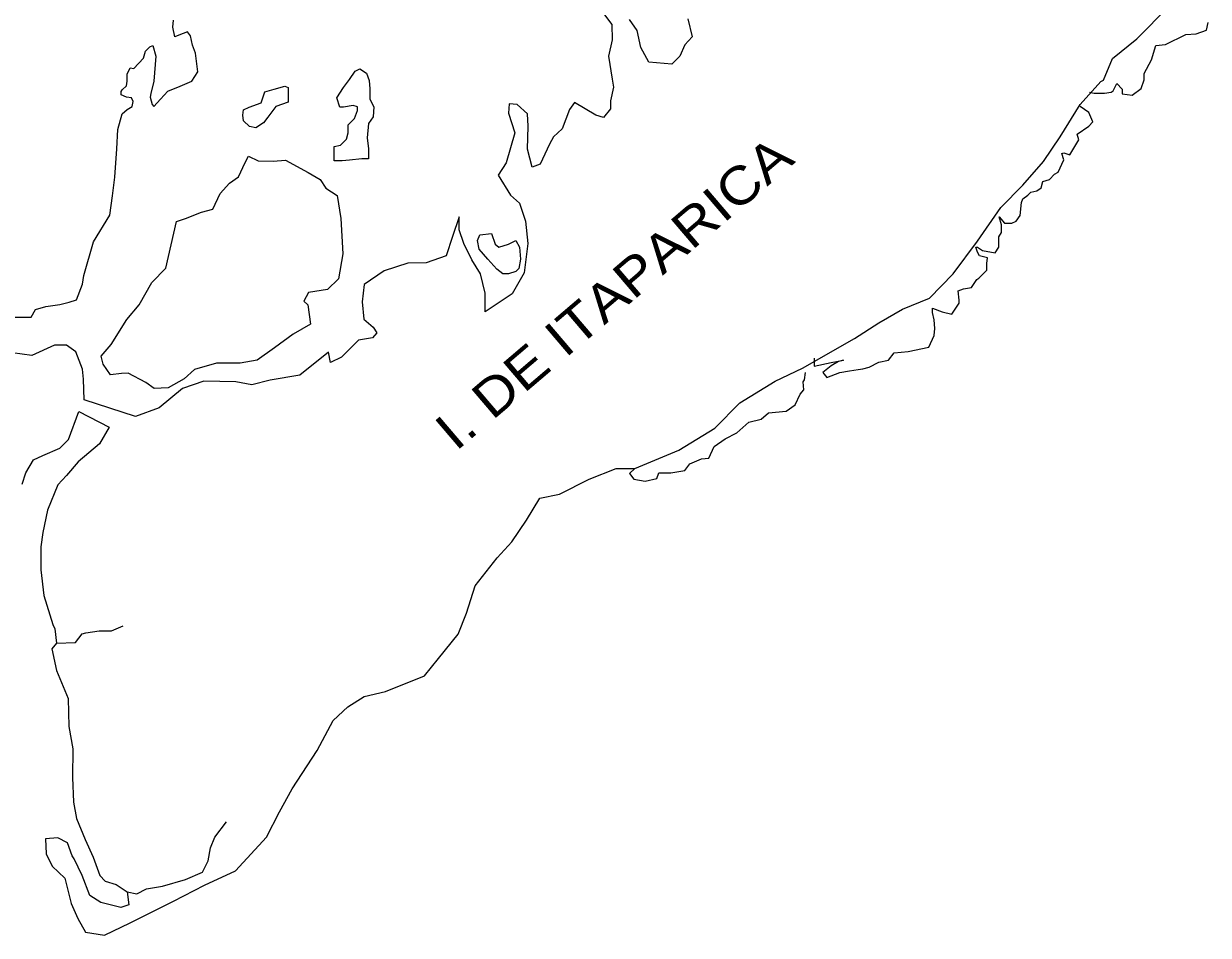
# Model space of a CAD drawing. Extents: x 47169 to 972804, y 7447977 to 9608469.
# Drawn here: x 521076 to 542158, y 8548311 to 8564537 of the extents above; entities that cross this region are included whole.
import ezdxf

# ---------------------------------------------------------------- set-up
doc = ezdxf.new("R2010")
doc.units = 0
doc.header["$LTSCALE"] = 270
doc.layers.add('1', color=7, linetype='Continuous', lineweight=13)
doc.layers.add('3', color=7, linetype='Continuous')

msp = doc.modelspace()

# ---------------------------------------------------------------- linework, layer by layer
at = {"layer": '1'}
for points in [[(524845.6, 8549458.9), (525398.9, 8550055.6), (525627, 8550508.8), (525855, 8550917.8), (526300.1, 8551603), (526582.5, 8552133.6), (526842.9, 8552376.7), (527135.8, 8552564.4), (527515.3, 8552652.4), (528209.3, 8552928.2), (528459, 8553237.6), (528806.4, 8553668.6), (528958.5, 8554044.4), (529110.8, 8554530.8), (529501.7, 8555028.1), (529762.2, 8555315.3), (530022.8, 8555702.1), (530261.8, 8556088.9), (530608.8, 8556165.9), (531140.3, 8556430.8), (531617.6, 8556618.2), (531953.7, 8556617.8), (532734.8, 8556948.7), (533374.9, 8557335), (533820.1, 8557787.8), (534449.4, 8558174.1), (534937.6, 8558405.7), (535860, 8558935.4), (536294.1, 8559211.3), (536717.3, 8559454), (537194.7, 8559652.5), (537618.2, 8560083.2), (538052.7, 8560668.7), (538465.6, 8561265.3), (538856.6, 8561662.9), (539225.9, 8562082.6), (539519.3, 8562524.6), (539878, 8563099.1), (540247.3, 8563507.8), (540290.8, 8563529.8), (540454, 8563916.7), (540888.3, 8564269.9), (541453.1, 8564844.1)], [(531355.8, 8564768.9), (531539.9, 8564525.4), (531550.4, 8564249), (531485.1, 8563961.5), (531549.7, 8563552.2), (531571.2, 8563408.5), (531516.7, 8563165.2), (531516.5, 8563021.5), (531397.1, 8562866.8), (531256.1, 8562911.2), (530876.8, 8563132.8), (530789.9, 8563011.2), (530659.4, 8562668.5), (530507.4, 8562524.9), (530431.3, 8562392.3), (530268.3, 8562038.6), (530127.2, 8561983.5), (530040.8, 8562304.3), (530052.1, 8562713.4), (530041.5, 8562934.6), (529857.3, 8563100.7), (529716.4, 8563111.9), (529705.3, 8562946.1), (529813.4, 8562592.1), (529661, 8562061.4), (529519.8, 8561840.4), (529736.3, 8561486.2), (529898.8, 8561342.3), (530006.9, 8561021.5), (530049.9, 8560623.3)], [(523991.4, 8564389.3), (523839.5, 8564334.1), (523763.6, 8564301), (523731.2, 8564477.9), (523742.2, 8564599.6)], [(532895.7, 8564623.4), (532971.2, 8564302.6), (532840.9, 8564159), (532753.9, 8563960), (532612.8, 8563816.4), (532200.7, 8563850.1), (532060, 8564115.7), (531995.3, 8564414.3), (531854.5, 8564613.6)], [(540041, 8563320.1), (540127.7, 8563297.8), (540312.1, 8563297.6), (540431.4, 8563319.5), (540464, 8563341.6), (540529.3, 8563474.2), (540626.7, 8563374.5), (540626.7, 8563341.3), (540626.6, 8563286), (540800.1, 8563263.7), (540962.9, 8563385.1), (541017.4, 8563539.8), (541017.6, 8563650.4), (541148.1, 8563893.5), (541224.3, 8564147.8), (541397.9, 8564169.6), (541756.1, 8564346), (541940.5, 8564356.8), (542124.9, 8564422.9), (542157.7, 8564555.5)], [(520907.5, 8559315.8), (521081, 8559315.6), (521135.2, 8559315.6), (521211.1, 8559315.5), (521287.2, 8559448.2), (521471.5, 8559503.3), (521721, 8559536.3), (521883.6, 8559580.4), (522013.8, 8559624.5), (522122.5, 8559900.9), (522144.3, 8560055.7), (522318.2, 8560652.8), (522611.4, 8561128.1), (522655.1, 8561470.8), (522698.7, 8561802.6), (522731.7, 8562311.3), (522753.6, 8562654.1), (522829.8, 8562930.5), (522916.6, 8563007.8), (523003.4, 8563063), (523025.2, 8563151.5), (522992.7, 8563217.9), (522905.9, 8563229), (522808.4, 8563273.3), (522808.4, 8563328.6), (522830.1, 8563361.8), (522906.1, 8563428.1), (522917, 8563516.5), (522917.1, 8563638.2), (522971.5, 8563748.7), (523036.5, 8563737.6), (523210.2, 8563925.4), (523242.8, 8564047.1), (523318.8, 8564124.4), (523373, 8564146.5), (523427.1, 8563958.4), (523394.2, 8563516.1), (523339.8, 8563295), (523328.9, 8563228.7), (523361.3, 8563095.9), (523393.8, 8563062.7), (523513.2, 8563195.3), (523643.5, 8563339), (523860.5, 8563427.3), (524066.6, 8563515.5), (524175.2, 8563681.3), (524132.1, 8564013.1), (524078, 8564156.9), (524045.6, 8564322.9), (523991.4, 8564389.3)], [(535143.9, 8558582.4), (535143.7, 8558438.7), (535447.4, 8558504.6), (535664.3, 8558548.6), (535577.5, 8558526.6), (535447.3, 8558449.3), (535295.4, 8558327.9), (535371.2, 8558239.3), (535599, 8558327.5), (535772.5, 8558360.4), (535924.3, 8558382.4), (536011.1, 8558393.3), (536119.6, 8558426.3), (536293.2, 8558514.6), (536466.7, 8558547.5), (536564.4, 8558680.1), (536813.9, 8558701.9), (537182.7, 8558778.8), (537280.5, 8558988.8), (537291.5, 8559110.4), (537280.9, 8559265.3), (537248.5, 8559398), (537248.7, 8559475.4), (537422.1, 8559408.9), (537595.5, 8559364.4), (537725.9, 8559563.3), (537726, 8559618.6), (537704.5, 8559784.5), (537802.1, 8559817.5), (537943.1, 8559839.4), (538040.9, 8559983.1), (538073.5, 8560005.2), (538214.7, 8560148.7), (538214.8, 8560270.4), (538225.8, 8560369.9), (538084.9, 8560403.3), (538052.4, 8560469.7), (538020, 8560558.2), (538052.6, 8560558.1), (538139.2, 8560502.7), (538366.9, 8560458.2), (538432.1, 8560557.6), (538432.2, 8560623.9), (538432.4, 8560745.6), (538475.8, 8560823), (538476, 8560955.7), (538432.8, 8561099.5), (538530.3, 8560988.8), (538660.4, 8560988.6), (538736.4, 8561021.7), (538812.4, 8561121.1), (538834.4, 8561353.3), (538856.2, 8561419.6), (538943.1, 8561485.8), (538997.4, 8561541.1), (539105.8, 8561563), (539181.8, 8561618.2), (539214.5, 8561728.8), (539333.9, 8561761.8), (539420.8, 8561861.2), (539485.9, 8561894.3), (539583.8, 8562115.3), (539551.4, 8562225.9), (539584, 8562236.9), (539692.4, 8562203.6), (539855.4, 8562468.8), (539823, 8562568.4), (540029.3, 8562711.8), (540105.3, 8562789.2), (540029.6, 8562955.1), (539878, 8563065.9)], [(530049.9, 8560623.3), (529984.2, 8560103.6), (529766.9, 8559727.8), (529289.5, 8559407.6), (529289.8, 8559739.4), (529203.5, 8560082.3), (529051.9, 8560336.8), (528911.3, 8560624.5), (528824.8, 8560867.9), (528825, 8561100.2), (528705.4, 8560746.4), (528596.6, 8560403.7), (528238.6, 8560282.4), (527913.3, 8560271.7), (527490.2, 8560139.4), (527132.2, 8559896.4), (527099.3, 8559586.8), (527131.5, 8559277.1), (527294.1, 8559133.2), (527359, 8559033.6), (527283, 8558945.2), (527033.6, 8558901.2), (526729.7, 8558602.9), (526534.4, 8558503.6), (526502.1, 8558691.6), (525992.1, 8558282.9), (525460.7, 8558195), (525135.3, 8558106.8), (524853.4, 8558162.3), (524278.8, 8558173.9), (523899.2, 8558041.5), (523486.9, 8557699.1), (523063.9, 8557544.6), (522153.3, 8557843.9), (522142.8, 8558208.9), (522121.2, 8558385.8), (522002.2, 8558695.6), (521839.7, 8558817.4), (521622.8, 8558817.6), (521221.5, 8558629.9), (520354.1, 8558752.2)], [(531953.7, 8556617.8), (531856.1, 8556529.5), (531931.8, 8556429.8), (532137.8, 8556396.4), (532343.8, 8556440.4), (532376.5, 8556539.9), (532593.3, 8556539.7), (532842.8, 8556583.6), (532929.6, 8556705.1), (533135.8, 8556793.4), (533265.9, 8556804.3), (533363.7, 8557014.3), (533559, 8557146.7), (533765.2, 8557257.1), (533982.3, 8557444.8), (534199.2, 8557499.8), (534329.4, 8557610.3), (534643.9, 8557643.1), (534806.7, 8557753.4), (534893.7, 8557941.3), (534958.8, 8558018.7), (534948.2, 8558162.4), (534969.9, 8558195.6), (534991.8, 8558328.3)], [(521046.2, 8556340.8), (521111.4, 8556539.8), (521252.5, 8556771.9), (521415.2, 8556849.2), (521718.9, 8556981.7), (521870.9, 8557136.4), (522055.6, 8557633.9), (522597.5, 8557357), (522423.8, 8557058.5), (522044, 8556738.1), (521837.8, 8556495), (521685.9, 8556329.2), (521501.2, 8555876), (521414.2, 8555477.9), (521381.5, 8555223.6), (521381.1, 8554814.4), (521435, 8554360.9), (521597.2, 8553841.1), (521629.7, 8553763.6), (521662, 8553509.2), (521575.2, 8553409.8), (521661.6, 8553022.7), (521867.2, 8552524.8), (521877.6, 8552027.2), (521953.2, 8551629), (521941.9, 8551120.3), (521963.3, 8550677.9), (522017.2, 8550390.3), (522168.7, 8550014.2), (522309.3, 8549704.4), (522428.3, 8549372.6), (522525.8, 8549273), (522720.8, 8549217.5), (522915.8, 8549084.6), (522948.2, 8548852.4), (522807.2, 8548808.3), (522449.6, 8548897), (522254.6, 8549018.8), (522114, 8549372.8), (521973.3, 8549671.5), (521940.8, 8549726.9), (521854.3, 8549959.2), (521680.9, 8550047.8), (521464.1, 8550025.8), (521474.8, 8549760.4), (521583, 8549539.1), (521810.4, 8549328.8), (521918.5, 8548875.3), (522037.5, 8548609.8), (522178.2, 8548366.4), (522514.2, 8548310.8), (522969.6, 8548531.6), (523739.5, 8548918.1), (524292.5, 8549205.1), (524845.6, 8549458.9)], [(521662, 8553509.2), (521998.1, 8553520), (522117.4, 8553674.8), (522182.5, 8553696.8), (522421, 8553729.8), (522637.9, 8553729.6), (522843.9, 8553817.9)], [(522915.8, 8549084.6), (523089.2, 8549051.3), (523262.7, 8549139.6), (523544.6, 8549183.6), (523956.6, 8549304.9), (524260.2, 8549437.4), (524357.9, 8549636.3), (524401.5, 8549868.5), (524477.6, 8550056.5), (524683.8, 8550332.8)]]:
    msp.add_lwpolyline(points, dxfattribs=at)
for points in [[(526875.5, 8563546.1), (526973.2, 8563689.8), (527060, 8563734), (527179.2, 8563656.4), (527222.5, 8563523.7), (527233.2, 8563379.9), (527233, 8563191.9), (527308.8, 8563059.1), (527297.8, 8562882.2), (527210.9, 8562760.6), (527188.9, 8562506.3), (527210.4, 8562307.2), (527210.3, 8562130.3), (527091, 8562130.4), (526874.1, 8562108.5), (526743.9, 8562097.5), (526602.9, 8562097.7), (526603.1, 8562241.4), (526603.2, 8562352), (526711.7, 8562374.1), (526820.2, 8562484.5), (526852.8, 8562595.1), (526853, 8562738.9), (526961.6, 8562849.3), (527015.9, 8562993.1), (527016, 8563059.4), (526940.1, 8563081.6), (526766.5, 8563048.6), (526701.5, 8563048.7), (526647.4, 8563214.6), (526766.9, 8563402.5)], [(525302.6, 8563127.4), (525367.8, 8563326.4), (525530.5, 8563370.5), (525725.8, 8563425.6), (525780, 8563403.4), (525779.7, 8563138), (525562.8, 8563060.8), (525421.6, 8562872.9), (525345.6, 8562773.4), (525204.6, 8562685.1), (525096.1, 8562707.3), (524987.8, 8562807), (524977, 8562906.5), (524987.9, 8563006), (525085.6, 8563050.2)], [(523608.3, 8560187.2), (523793.3, 8561016.5), (523956, 8561071.6), (524238.1, 8561182), (524444.1, 8561237.1), (524574.5, 8561513.4), (524737.3, 8561701.3), (524900.1, 8561811.7), (525019.6, 8562066), (525073.9, 8562176.5), (525247.4, 8562098.9), (525518.5, 8562087.7), (525735.4, 8562109.6), (526136.4, 8561888), (526353.2, 8561766.2), (526450.7, 8561611.2), (526656.6, 8561478.3), (526721.2, 8561069.1), (526753.2, 8560438.7), (526676.8, 8559996.4), (526481.5, 8559808.6), (526145.2, 8559753.6), (526058.4, 8559598.9), (526134.2, 8559532.5), (526177.2, 8559189.6), (525873.5, 8559012.9), (525537.1, 8558770), (525233.3, 8558549.1), (524929.6, 8558494.1), (524506.8, 8558494.4), (524116.3, 8558384.2), (523931.9, 8558218.4), (523649.8, 8558052.8), (523400.4, 8558042), (523248.7, 8558152.7), (522934.4, 8558318.8), (522815.1, 8558307.9), (522619.9, 8558285.9), (522490, 8558474), (522457.5, 8558617.8), (522631.2, 8558827.8), (522913.5, 8559269.9), (523130.6, 8559535.1), (523358.6, 8559933.1)], [(529182.2, 8560524.7), (529149.9, 8560679.6), (529193.4, 8560779.1), (529399.4, 8560800.9), (529464.3, 8560612.9), (529529.3, 8560557.5), (529702.8, 8560612.6), (529833.1, 8560678.8), (529898, 8560557.1), (529919.4, 8560347), (529886.7, 8560181.1), (529832.4, 8560125.9), (529702.3, 8560081.8), (529604.7, 8560081.9), (529496.3, 8560170.5), (529333.9, 8560347.6)]]:
    msp.add_lwpolyline(points, close=True, dxfattribs=at)

# ---------------------------------------------------------------- texts
at = {"layer": '3', "width": 1.15}
msp.add_text('I. DE ITAPARICA', height=665.6, rotation=40.451, dxfattribs=at).set_placement((528765.7, 8556912.1))

doc.saveas('drawing.dxf')
